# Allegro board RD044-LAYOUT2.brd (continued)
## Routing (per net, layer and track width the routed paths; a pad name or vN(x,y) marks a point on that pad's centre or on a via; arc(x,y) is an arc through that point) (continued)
/DI0_BI: length 29.5
  TOP w0.15: R74.2 18.75,3.7 18.75,9.75 19.73,10.72 19.73,11.07 ; 19.5,2.85 v1(19.5,1.9) ; 34.75,1.5 v3(34.75,2.1)
  TOP w0.25: CN3.51 34.75,1.5
  TOP w0.35: 19.73,11.07 IC11.2
  TOP w0.8: R74.2 19.5,2.85
  BOTTOM w0.15: v1(19.5,1.9) 21.5,3.9 32.15,3.9 32.35,4.1 34.4,4.1 34.75,3.75 v3(34.75,2.1)
/DI1_BI: length 22.5
  TOP w0.15: 34.75,5.85 34.75,6.75 32.7,8.8 v1(30.5,8.8) ; 19.5,8.65 v1(19.5,9.6) 20.38,10.47 20.38,11.07
  TOP w0.25: CN3.52 34.75,5.85
  TOP w0.35: 20.38,11.07 IC11.3
  TOP w0.8: R75.2 19.5,8.65
  BOTTOM w0.15: v1(30.5,8.8) 28.2,8.8 26,11 20.9,11 v1(19.5,9.6)
/DI2_BI: length 26.6
  TOP w0.15: 34.25,1.5 v3(34.25,3) ; 21.5,2.85 v1(21.5,1.9) ; 21.02,11.07 21.02,10.53 20.5,10 20.5,3.95 R76.2
  TOP w0.25: CN3.53 34.25,1.5
  TOP w0.35: 21.02,11.07 IC11.4
  TOP w0.8: R76.2 21.5,2.85
  BOTTOM w0.15: v3(34.25,3) 34.25,3.55 34,3.8 32.55,3.8 32.35,3.6 23.2,3.6 v1(21.5,1.9)
/DI3_BI: length 19.5
  TOP w0.15: 21.5,8.65 v1(21.5,9.6) 21.68,9.88 21.68,11.07 ; v1(31.5,8.2) 32.8,8.2 34.25,6.75 34.25,5.85
  TOP w0.25: CN3.54 34.25,5.85
  TOP w0.35: 21.68,11.07 IC11.5
  TOP w0.8: R77.2 21.5,8.65
  BOTTOM w0.15: v1(21.5,9.6) 22.6,10.7 25.8,10.7 28.3,8.2 v1(31.5,8.2)
/DI4_BI: length 23.5
  TOP w0.15: 22.32,11.07 22.32,9.93 22.5,9.75 22.5,3.95 R78.2 ; 33.75,1.5 v3(33.75,2.1) ; 23.5,2.85 v1(23.5,1.9)
  TOP w0.25: CN3.55 33.75,1.5
  TOP w0.35: 22.32,11.07 IC11.6
  TOP w0.8: R78.2 23.5,2.85
  BOTTOM w0.15: v1(23.5,1.9) 24.9,3.3 32.55,3.3 32.75,3.5 33.5,3.5 33.75,3.25 v3(33.75,2.1)
/DI5_BI: length 16.8
  TOP w0.15: 23.5,8.65 v1(23.5,9.6) 22.98,10.12 22.98,11.07 ; v1(30.5,7.6) 32.85,7.6 33.75,6.7 33.75,5.85
  TOP w0.25: CN3.56 33.75,5.85
  TOP w0.35: 22.98,11.07 IC11.7
  TOP w0.8: R79.2 23.5,8.65
  BOTTOM w0.15: v1(23.5,9.6) 24.25,10.35 25.65,10.35 28.4,7.6 v1(30.5,7.6)
/DI6_BI: length 20.8
  TOP w0.15: 33.25,1.5 v3(33.25,3) ; R80.2 24.5,3.95 24.5,10 23.62,10.88 23.62,11.07 ; 25.5,2.85 v1(25.5,1.9)
  TOP w0.25: CN3.57 33.25,1.5
  TOP w0.35: 23.62,11.07 IC11.8
  TOP w0.8: R80.2 25.5,2.85
  BOTTOM w0.15: v3(33.25,3) 26.6,3 v1(25.5,1.9)
/DI7_BI: length 14
  TOP w0.15: 33.25,5.85 33.25,6.75 33,7 v1(31.5,7) ; 25.5,8.65 v1(25.5,9.6) 24.27,10.82 24.27,11.07
  TOP w0.25: CN3.58 33.25,5.85
  TOP w0.35: 24.27,11.07 IC11.9
  TOP w0.8: R82.2 25.5,8.65
  BOTTOM w0.15: v1(25.5,9.6) 28.1,7 v1(31.5,7)
/DO0_BO: length 28.2
  TOP w0.15: 38.07,20.01 37.21,20.01 34.7,17.5 v1(33.5,17.5) 31,17.5 PAD8.1 ; 37.25,1.5 v3(37.25,3)
  TOP w0.25: CN3.41 37.25,1.5
  TOP w0.5: IC7.11 38.07,20.01
  BOTTOM w0.15: v3(37.25,3) 37.25,3.75 36.65,4.35 36.65,10.6 35.9,11.35 35.9,12.6 35.3,13.2 35.3,15.7 v1(33.5,17.5)
/DO1_BO: length 20.6
  TOP w0.15: 37.25,5.85 37.25,7 36.35,7.9 36.35,10.15 v3(36,10.5) ; 38.08,19.27 37.08,19.27 34.3,16.5 v1(33.5,16.5) PAD7.1
  TOP w0.25: CN3.42 37.25,5.85
  TOP w0.35: IC7.12 38.08,19.27
  BOTTOM w0.15: v3(36,10.5) 35.6,10.9 35.6,12.4 35,13 35,15 v1(33.5,16.5)
/DO2_BO: length 26.4
  TOP w0.15: 36.75,1.5 v3(36.75,2.1) ; PAD6.1 31,15.5 v1(33.5,15.5) 33.9,15.5 37.02,18.62 38.08,18.62
  TOP w0.25: CN3.43 36.75,1.5
  TOP w0.35: IC7.13 38.08,18.62
  BOTTOM w0.15: v3(36.75,2.1) 36.75,3.75 36.35,4.15 36.35,9.65 36,10 35.75,10 35.3,10.45 35.3,12.2 34.7,12.8 34.7,14.3 v1(33.5,15.5)
/DO3_BO: length 18.7
  TOP w0.15: 36.75,5.85 36.75,7 36.05,7.7 36.05,9.2 v3(35.75,9.5) ; PAD5.1 v1(33.5,14.5) 36.98,17.98 38.08,17.98
  TOP w0.25: CN3.44 36.75,5.85
  TOP w0.35: IC7.14 38.08,17.98
  BOTTOM w0.15: v3(35.75,9.5) 35,10.25 35,12 34.4,12.6 34.4,13.6 v1(33.5,14.5)
/DO4_BO: length 24.7
  TOP w0.15: 36.25,1.5 v3(36.25,3) ; 38.08,17.32 36.92,17.32 34.2,14.6 34.2,14.2 v1(33.5,13.5) 31,13.5 PAD4.1
  TOP w0.25: CN3.45 36.25,1.5
  TOP w0.35: IC7.15 38.08,17.32
  BOTTOM w0.15: v1(33.5,13.5) 34.1,12.9 34.1,12.4 34.7,11.8 34.7,9.8 35.5,9 35.75,9 36.05,8.7 36.05,3.95 36.25,3.75 v3(36.25,3)
/DO5_BO: length 17.2
  TOP w0.15: 38.08,16.68 36.88,16.68 34.6,14.4 34.6,13.6 v1(33.5,12.5) PAD3.1 ; v3(35.5,8.5) 35.75,8.25 35.75,7.5 36.25,7 36.25,5.85
  TOP w0.25: CN3.46 36.25,5.85
  TOP w0.35: IC7.16 38.08,16.68
  BOTTOM w0.15: v1(33.5,12.5) 34.4,11.6 34.4,9.6 v3(35.5,8.5)
/DO6_BO: length 23.2
  TOP w0.15: 35.75,1.5 v3(35.75,2.1) ; PAD2.1 31,11.5 v1(33.5,11.5) 35,13 35,14.2 36.83,16.02 38.08,16.02
  TOP w0.25: CN3.47 35.75,1.5
  TOP w0.35: IC7.17 38.08,16.02
  BOTTOM w0.15: v1(33.5,11.5) 34.1,10.9 34.1,9.15 35.25,8 35.5,8 35.75,7.75 v3(35.75,2.1)
/DO7_BO: length 15.8
  TOP w0.15: PAD1.1 v1(33.5,10.5) 35.4,12.4 35.4,14 36.77,15.38 38.08,15.38 ; 35.75,5.85 35.75,7 v3(35.25,7.5)
  TOP w0.25: CN3.48 35.75,5.85
  TOP w0.35: IC7.18 38.08,15.38
  BOTTOM w0.15: v3(35.25,7.5) 33.5,9.25 v1(33.5,10.5)
/PWM1A_BO: length 61.1
  TOP w0.15: 38.08,38.62 37.38,38.62 v1(36.5,39.5) 36.5,41.5 35.75,42.25 35.75,45.25 35,46 29.25,46 29,45.75 TP6.1 ; 41.25,1.5 v3(41.25,3)
  TOP w0.25: CN3.25 41.25,1.5
  TOP w0.35: IC5.13 38.08,38.62
  BOTTOM w0.15: v3(41.25,3) 41.25,6.75 41.75,7.25 41.75,9.75 44.65,12.65 44.65,30.85 42.45,33.05 41.05,33.05 40.75,33.35 40.75,35.25 v1(36.5,39.5)
/PWM1B_BO: length 47.9
  TOP w0.15: 38.08,37.98 37.02,37.98 v1(36.5,38.5) 35.9,39.1 35.9,41.1 34,43 TP5.1 ; 41.25,5.85 v3(41.25,9.2)
  TOP w0.25: CN3.26 41.25,5.85
  TOP w0.35: IC5.14 38.08,37.98
  BOTTOM w0.15: v3(41.25,9.2) 41.25,9.85 44.2,12.8 44.2,30.8 42.4,32.6 40.9,32.6 40.3,33.2 40.3,34.7 v1(36.5,38.5)
/PWM2A_BO: length 55.9
  TOP w0.15: TP4.1 29,40.75 29.25,41 35.25,41 35.5,40.75 35.5,38.5 v1(36.5,37.5) 36.78,37.33 38.08,37.33 ; 40.75,1.5 v3(40.75,2.1)
  TOP w0.25: CN3.27 40.75,1.5
  TOP w0.35: IC5.15 38.08,37.33
  BOTTOM w0.15: v1(36.5,37.5) 39.85,34.15 39.85,33.05 40.75,32.15 42.35,32.15 43.75,30.75 43.75,12.95 40.75,9.95 40.75,9 41.25,8.5 41.25,7.25 40.75,6.75 v3(40.75,2.1)
/PWM2B_BO: length 43
  TOP w0.15: 38.08,36.67 36.78,36.67 v1(36.5,36.5) 35.75,36.5 34,38.25 TP3.1 ; 40.75,5.85 v3(40.75,8.3)
  TOP w0.25: CN3.28 40.75,5.85
  TOP w0.35: IC5.16 38.08,36.67
  BOTTOM w0.15: v1(36.5,36.5) 39.4,33.6 39.4,32.9 40.6,31.7 42.3,31.7 43.3,30.7 43.3,13.1 40.45,10.25 40.45,8.6 v3(40.75,8.3)
/PWM3A_BO: length 52.1
  TOP w0.15: 40.25,1.5 v3(40.25,3) ; 38.08,36.02 37.02,36.02 v1(36.5,35.5) 36,36 29.25,36 29,35.75 TP2.1
  TOP w0.25: CN3.29 40.25,1.5
  TOP w0.35: IC5.17 38.08,36.02
  BOTTOM w0.15: v1(36.5,35.5) 37.8,34.2 37.8,32.3 38.85,31.25 42.25,31.25 42.85,30.65 42.85,13.25 40.15,10.55 40.15,8.2 40.75,7.6 40.75,7.2 40.25,6.7 v3(40.25,3)
/PWM3B_BO: length 40
  TOP w0.15: 40.25,5.85 v3(40.25,7.4) ; 38.08,35.38 37.38,35.38 v1(36.5,34.5) 34.15,34.5
  TOP w0.25: CN3.30 40.25,5.85
  TOP w0.35: IC5.18 38.08,35.38
  TOP w1.7: TP1.1 34.15,34.5
  BOTTOM w0.15: v1(36.5,34.5) 37.35,33.65 37.35,32.15 38.7,30.8 42.2,30.8 42.4,30.6 42.4,13.4 39.85,10.85 39.85,7.8 v3(40.25,7.4)
/PWM4A_BO: length 42.9
  TOP w0.15: TP12.1 29,30.75 29.25,31 35,31 v1(36.5,29.5) 37.38,28.62 38.08,28.62 ; 39.25,1.5 v3(39.25,3)
  TOP w0.25: CN3.33 39.25,1.5
  TOP w0.35: IC6.13 38.08,28.62
  BOTTOM w0.15: v1(36.5,29.5) 40.8,25.2 40.8,12.4 39.4,11 39.4,7 39.25,6.85 v3(39.25,3)
/PWM4B_BO: length 30.8
  TOP w0.15: 39.25,5.85 39.25,9.15 v3(38.9,9.5) ; 38.08,27.98 37.02,27.98 v1(36.5,28.5) 35.5,29.5 TP11.1
  TOP w0.25: CN3.34 39.25,5.85
  TOP w0.35: IC6.14 38.08,27.98
  BOTTOM w0.15: v1(36.5,28.5) 40.35,24.65 40.35,12.55 38.9,11.1 v3(38.9,9.5)
/PWM5A_BO: length 40.6
  TOP w0.15: TP10.1 29,25.75 30.75,27.5 v1(36.5,27.5) 36.78,27.32 38.08,27.32 ; 38.75,1.5 v3(38.75,2.1)
  TOP w0.25: CN3.35 38.75,1.5
  TOP w0.35: IC6.15 38.08,27.32
  BOTTOM w0.15: v3(38.75,2.1) 38.75,6.85 39,7.1 39,8.5 38.4,9.1 38.4,11.2 39.9,12.7 39.9,24.1 v1(36.5,27.5)
/PWM5B_BO: length 29.6
  TOP w0.15: TP9.1 34,25.75 34.75,26.5 v1(36.5,26.5) 36.78,26.68 38.08,26.68 ; v3(38.3,8.5) 38.75,8.05 38.75,5.85
  TOP w0.25: CN3.36 38.75,5.85
  TOP w0.35: IC6.16 38.08,26.68
  BOTTOM w0.15: v1(36.5,26.5) 39.45,23.55 39.45,12.85 38.05,11.45 38.05,8.75 v3(38.3,8.5)
/PWM6A_BO: length 39.5
  TOP w0.15: 38.25,1.5 v3(38.25,3) ; 38.08,26.02 37.02,26.02 v1(36.5,25.5) 35.5,24.5 35.5,23 34.25,21.75 30,21.75 29,20.75 TP8.1
  TOP w0.25: CN3.37 38.25,1.5
  TOP w0.35: IC6.17 38.08,26.02
  BOTTOM w0.15: v3(38.25,3) 38.25,6.85 38.5,7.1 38.5,7.6 37.7,8.4 37.7,11.7 37.8,11.8 37.8,24.2 v1(36.5,25.5)
/PWM6B_BO: length 28.5
  TOP w0.15: 38.25,5.85 38.25,7.15 v3(38,7.4) ; 38.08,25.38 37.38,25.38 v1(36.5,24.5) 35.9,23.9 35.9,22.65 34,20.75 TP7.1
  TOP w0.25: CN3.38 38.25,5.85
  TOP w0.35: IC6.18 38.08,25.38
  BOTTOM w0.15: v1(36.5,24.5) 37.35,23.65 37.35,8.05 v3(38,7.4)
/RESET_BO: length 52.3
  TOP w0.15: 38.46,42.3 37.7,42.3 37,43 PAD9.1 ; 38.55,42.05 v1(38.55,41) ; 35.25,1.5 v3(35.25,3)
  TOP w0.25: CN3.49 35.25,1.5
  TOP w0.5: 38.55,42.05 IC8.4 38.46,42.3
  BOTTOM w0.15: v1(38.55,41) 35,41 31.5,37.5 31.5,9.5 35.25,5.75 v3(35.25,3)
/RESET_SIG: length 34.5
  TOP w0.15: 59.25,53.13 v1(59.25,52)
  TOP w0.25: IC3.124 59.25,53.13 ; 39.5,44.95 v1(39.5,46)
  TOP w0.5: IC8.2 39.5,44.95
  BOTTOM w0.25: 37.3,52.1 37.3,48.2 v1(39.5,46) 41.5,48 52.25,48 57,52.75 58.5,52.75 v1(59.25,52) ; 37.3,52.36 37.3,53.35 37.45,53.5 IC2.4
  BOTTOM w0.8: 37.3,52.1 R7.2 37.3,52.36
AD0: length 47.4
  TOP w0.15: 45.25,1.5 v3(45.25,3)
  TOP w0.25: CN3.9 45.25,1.5
  BOTTOM w0.2: R50.2 78,4.2 54.6,4.2 50.1,8.7 46.3,8.7 45.45,7.85 45.45,4.45 45.25,4.25 v3(45.25,3)
AD1: length 55.5
  TOP w0.2: v1(83.5,7) 80.7,4.2 54.8,4.2 50.3,8.7 46.3,8.7 45.25,7.65 45.25,5.88
  TOP w0.25: CN3.10 45.25,5.88
  BOTTOM w0.2: v1(83.5,7) 83.5,16.2 R54.2
AD2: length 48.4
  TOP w0.15: 44.25,1.5 v3(44.25,3)
  TOP w0.25: CN3.13 44.25,1.5
  BOTTOM w0.2: v3(44.25,3) 44.25,4.75 44.55,5.05 44.55,8.25 46,9.7 50.7,9.7 55.2,5.2 69.45,5.2 70.5,6.25 70.5,16.2 R55.1
AD3: length 35
  TOP w0.2: 44.25,5.88 44.25,7.95 46,9.7 50.9,9.7 55.4,5.2 70.2,5.2 v1(72,7)
  TOP w0.25: CN3.14 44.25,5.88
  BOTTOM w0.2: 72,8.07 v1(72,7)
  BOTTOM w0.8: R51.1 72,8.07
AD4: length 35.3
  TOP w0.15: 43.25,1.5 v3(43.25,3)
  TOP w0.25: CN3.17 43.25,1.5
  BOTTOM w0.2: v3(43.25,3) 43.25,5.25 43.65,5.65 43.65,8.65 45.7,10.7 51.3,10.7 55.8,6.2 65.5,6.2 R62.2
AD5: length 43.2
  TOP w0.2: v1(68.75,7) 67.95,6.2 56,6.2 51.5,10.7 45.7,10.7 43.25,8.25 43.25,5.88
  TOP w0.25: 43.25,5.88 CN3.18
  BOTTOM w0.2: v1(68.75,7) 69,7.25 69,16.2 R66.2
AD6: length 28.5
  TOP w0.15: 42.25,1.5 v3(42.25,3)
  TOP w0.25: CN3.21 42.25,1.5
  BOTTOM w0.2: v3(42.25,3) 42.25,5.75 42.75,6.25 42.75,9.05 45.4,11.7 54.7,11.7 56.25,13.25 56.25,16.45 R67.1
AD7: length 21.3
  TOP w0.2: v1(56,8.2) 52.5,11.7 45.4,11.7 42.25,8.55 42.25,5.88
  TOP w0.25: 42.25,5.88 CN3.22
  BOTTOM w0.2: 57.37,8.2 v1(56,8.2)
  BOTTOM w0.8: R63.1 57.37,8.2
ADC01_P_DSP41: length 5.4
  TOP w0.2: 77.37,26.3 75.95,26.3 75.25,27 75.25,27.83 ; 78.87,26.3 77.63,26.3
  TOP w0.25: 75.25,27.83 IC3.41
  TOP w0.8: 77.37,26.3 C63.1 77.63,26.3 ; R58.1 78.87,26.3
ADC02_P_DSP39: length 5.4
  TOP w0.2: 74.63,24.55 75.87,24.55 ; 74.5,24.59 74.5,25.5 74.25,25.75 74.25,27.83
  TOP w0.25: 74.25,27.83 IC3.39
  TOP w0.8: 75.87,24.55 R60.1 ; 74.63,24.55 C65.1 74.5,24.59
ADC03_P_DSP48: length 3.9
  TOP w0.2: C64.1 79.95,31.75 79.17,31.75 ; 80.7,30.97 80.7,29.63
  TOP w0.25: IC3.48 79.17,31.75
  TOP w0.8: 80.7,29.63 R59.1 ; C64.1 80.7,30.97
ADC04_P_DSP44: length 6.6
  TOP w0.2: C66.1 79.6,27.2 77.05,27.2 76.81,27.43 76.81,27.79 ; 81.87,26.3 80.63,26.3
  TOP w0.35: 76.81,27.79 IC3.44
  TOP w0.8: 80.63,26.3 C66.1 ; R61.1 81.87,26.3
ADC05_P_DSP31: length 13.2
  TOP w0.2: 70.25,27.83 v1(70.25,25.75) 70,25.5 70,24.59 ; v1(75.25,25.75) 74.75,26.25 74.75,27.83 ; 68.63,24.55 69.87,24.55
  TOP w0.25: IC3.31 70.25,27.83 ; IC3.40 74.75,27.83
  TOP w0.8: 70,24.59 C72.1 69.87,24.55 ; R70.1 68.63,24.55
  BOTTOM w0.2: v1(70.25,25.75) v1(75.25,25.75)
ADC06_P_DSP29: length 32.2
  TOP w0.2: 65.63,24.55 66.87,24.55 ; v1(84.25,26.5) 84.25,31.25 83.25,32.25 79.17,32.25 ; C74.1 68.2,25.75 68.5,25.75 v1(69.25,26.5) 69.25,27.83
  TOP w0.25: IC3.29 69.25,27.83 ; 79.17,32.25 IC3.49
  TOP w0.8: R72.1 65.63,24.55 ; 66.87,24.55 C74.1
  BOTTOM w0.2: v1(84.25,26.5) v1(69.25,26.5)
ADC07_P_DSP56: length 7.8
  TOP w0.2: C73.1 83.55,36 80,36 79.75,35.75 79.17,35.75 ; 84.63,35.05 85.87,35.05
  TOP w0.25: 79.17,35.75 IC3.56
  TOP w0.8: 85.87,35.05 R71.1 ; C73.1 84.63,35.05
ADC08_P_DSP58: length 7.3
  TOP w0.2: 85.88,36.75 84.62,36.75 ; 84.38,36.75 79.17,36.75
  TOP w0.25: IC3.58 79.17,36.75
  TOP w0.7: 84.62,36.75 84.38,36.75 ; 86,36.75 85.88,36.75
BOOT1_DSP: length 30.1
  TOP w0.15: 34.66,61.13 33.87,61.13 33.75,61.25 33.15,61.25 ; 33.15,62.75 v1(34.5,62.75) ; 33.05,62.65 33.05,61.35
  TOP w0.7: SW2.3 34.66,61.13
  TOP w0.8: 33.05,61.35 R29.2 33.15,61.25 ; 33.15,62.75 R17.2 33.05,62.65
  BOTTOM w0.15: CN2.14 51.12,72.5 39.4,72.5 38.55,71.65 38.55,66.8 v1(34.5,62.75)
BOOT1_DSP139: length 34.3
  TOP w0.15: 52.83,48.75 52.25,48.75 52,48.5 47.9,48.5 44.8,51.6 v1(32,51.6) ; 31.35,61.25 v1(30.25,61.25)
  TOP w0.25: IC3.139 52.83,48.75
  TOP w0.8: R29.1 31.35,61.25
  BOTTOM w0.15: v1(32,51.6) 32,59.5 v1(30.25,61.25)
CANRX_A_DSP83: length 74.4
  TOP w0.15: 79.17,49.25 79.55,49.25 79.9,49.6 82.85,49.6 83.4,50.15 83.4,52.1 82.7,52.8 78.45,52.8 77.8,53.45 77.8,58.2 76.5,59.5 67.6,59.5 67.2,59.9 66.35,59.9 60.75,65.5 30,65.5 28.4,63.9 28.4,62.1 28.2,61.91 27.57,61.91
  TOP w0.25: 79.17,49.25 IC3.83
  TOP w0.6: IC12.4 27.57,61.91
CANTX_A_DSP84: length 80.4
  TOP w0.15: 28.3,56.6 28.3,57.9 28.11,58.09 27.57,58.09 ; 28.4,56.5 29.25,56.5 29.7,56.95 29.7,64.7 30.2,65.2 60.6,65.2 66.2,59.6 67.05,59.6 67.45,59.2 76.35,59.2 77.5,58.05 77.5,53.25 78.25,52.5 82.55,52.5 83.1,51.95 83.1,50.3 82.7,49.9 79.65,49.9 79.5,49.75 79.17,49.75
  TOP w0.25: IC3.84 79.17,49.75
  TOP w0.6: IC12.1 27.57,58.09
  TOP w0.8: 28.4,56.5 R83.2 28.3,56.6
CLK_20MHZ: length 2.9
  TOP w0.25: 59.75,56.35 IC3.123
  TOP w0.8: 59.75,56.5 59.75,56.35
DI0_DSP132: length 70
  TOP w0.15: 20.38,17.93 20.38,19.27 20.15,19.5 19.5,19.5 19,20 19,21.25 PAD10.1 21.95,24.2 24.45,24.2 25,24.75 25,49.5 28.6,53.1 35.4,53.1 36,52.5 55.05,52.5 55.19,52.63 55.19,53.11
  TOP w0.35: 55.19,53.11 IC3.132 ; IC11.18 20.38,17.93
DI1_DSP133: length 65.9
  TOP w0.15: 21.02,17.93 21.02,19.23 PAD11.1 20.85,21.1 20.85,22.6 22.15,23.9 24.6,23.9 25.3,24.6 25.3,49.3 28.8,52.8 35.2,52.8 35.8,52.2 51.93,52.2 52.31,51.81 52.81,51.81
  TOP w0.35: IC11.17 21.02,17.93 ; 52.81,51.81 IC3.133
DI2_DSP140: length 64.6
  TOP w0.15: 21.68,17.93 21.68,19.07 21.15,19.6 21.15,21.4 PAD12.1 23.35,23.6 24.75,23.6 25.6,24.45 25.6,49.1 27.5,51 44.5,51 47.65,47.85 52.05,47.85 52.45,48.25 52.83,48.25
  TOP w0.25: 52.83,48.25 IC3.140
  TOP w0.35: IC11.16 21.68,17.93
DI3_DSP141: length 63.6
  TOP w0.15: 22.32,17.93 22.32,18.98 22,19.3 PAD13.1 22.85,21.1 22.85,22.6 23.55,23.3 24.9,23.3 25.9,24.3 25.9,48.9 27.7,50.7 44.3,50.7 47.45,47.55 52.25,47.55 52.45,47.75 52.83,47.75
  TOP w0.25: 52.83,47.75 IC3.141
  TOP w0.35: IC11.15 22.32,17.93
DI4_DSP142: length 62
  TOP w0.15: 22.98,17.93 22.98,19.12 23.15,19.3 23.15,21.4 PAD14.1 24.75,23 25.05,23 26.2,24.15 26.2,48.7 27.9,50.4 44.1,50.4 47.25,47.25 52.83,47.25
  TOP w0.25: 52.83,47.25 IC3.142
  TOP w0.35: IC11.14 22.98,17.93
DI5_DSP143: length 61.2
  TOP w0.15: 23.62,17.93 23.62,18.88 24,19.25 PAD15.1 24.85,21.1 24.85,22.35 26.5,24 26.5,48.5 28.1,50.1 43.9,50.1 47.05,46.95 52.25,46.95 52.45,46.75 52.83,46.75
  TOP w0.25: 52.83,46.75 IC3.143
  TOP w0.35: IC11.13 23.62,17.93
DI6_DSP144: length 60.6
  TOP w0.15: 52.83,46.25 52.45,46.25 52.05,46.65 46.85,46.65 43.7,49.8 28.3,49.8 26.8,48.3 26.8,23.05 PAD16.1 25.15,21.4 25.15,19.9 24.27,19.02 24.27,17.93
  TOP w0.25: 52.83,46.25 IC3.144
  TOP w0.35: IC11.12 24.27,17.93
DI7_DSP145: length 59.9
  TOP w0.15: 25.01,17.93 25.01,19.26 PAD17.1 27.1,21.35 27.1,48.1 28.5,49.5 40.5,49.5 41.3,48.7 44.3,48.7 46.65,46.35 51.85,46.35 52.45,45.75 52.83,45.75
  TOP w0.25: 52.83,45.75 IC3.145
  TOP w0.5: IC11.11 25.01,17.93
DIO08_DSP94: length 69.3
  TOP w0.15: 13.9,38 15.69,38 ; 74.25,53.13 v1(74.25,52) ; 15.8,38.11 v1(15.8,39.2)
  TOP w0.25: IC3.94 74.25,53.13
  TOP w0.8: R96.2 13.9,38
  TOP w0.9: 15.69,38 D17.K/A 15.8,38.11
  BOTTOM w0.15: 16.7,39.2 v1(15.8,39.2) ; R88.2 17.9,40.3 27.8,40.3 32.6,45.1 51,45.1 52.1,46.2 57.95,46.2 61.85,50.1 69.35,50.1 72.15,52.9 73.35,52.9 v1(74.25,52)
  BOTTOM w0.8: R88.2 16.7,39.2
DIO09_DSP95: length 72
  TOP w0.15: 13.9,36 19.75,36 20.8,37.05 20.8,37.89 ; 20.8,38.11 v1(20.8,39.2) ; v1(73.65,51) 73.65,52.35 73.75,52.45 73.75,53.13
  TOP w0.25: IC3.95 73.75,53.13
  TOP w0.8: R98.2 13.9,36
  TOP w0.9: 20.8,37.89 D18.K/A 20.8,38.11
  BOTTOM w0.15: v1(73.65,51) 73.65,52.15 73.2,52.6 72.35,52.6 69.55,49.8 62.05,49.8 58.15,45.9 52.25,45.9 51.15,44.8 32.8,44.8 28,40 22.6,40 R89.2 ; 21.7,39.2 v1(20.8,39.2)
  BOTTOM w0.8: R89.2 21.7,39.2
DIO10_DSP96: length 69.1
  TOP w0.15: v1(73.05,52) 73.05,52.45 73.25,52.65 73.25,53.13 ; 13.9,34 15.69,34 ; 15.8,34.11 v1(15.8,35.2)
  TOP w0.25: IC3.96 73.25,53.13
  TOP w0.8: R99.2 13.9,34
  TOP w0.9: 15.8,34.11 D19.K/A 15.69,34
  BOTTOM w0.15: 16.7,35.2 v1(15.8,35.2) ; R90.2 17.9,36.3 24.8,36.3 33,44.5 51.3,44.5 52.4,45.6 58.35,45.6 62.25,49.5 69.75,49.5 72.25,52 v1(73.05,52)
  BOTTOM w0.8: R90.2 16.7,35.2
DIO11_DSP97: length 70.6
  TOP w0.15: 72.75,53.13 72.75,52.65 72.45,52.35 v1(72.45,51) ; 20.8,33.89 20.8,33.05 19.75,32 13.9,32 ; 20.8,34.11 v1(20.8,35.2)
  TOP w0.25: IC3.97 72.75,53.13
  TOP w0.8: R97.2 13.9,32
  TOP w0.9: 20.8,34.11 D20.K/A 20.8,33.89
  BOTTOM w0.15: R91.2 22.6,36 25,36 33.2,44.2 51.45,44.2 52.55,45.3 58.55,45.3 62.45,49.2 69.95,49.2 71.75,51 v1(72.45,51) ; 21.7,35.2 v1(20.8,35.2)
  BOTTOM w0.8: R91.2 21.7,35.2
DIO12_DSP171: length 56.3
  TOP w0.15: 15.8,30.11 v1(15.8,31.2) ; 52.83,32.75 52.5,32.75 v1(51.75,32) ; 13.9,30 15.69,30
  TOP w0.25: IC3.171 52.83,32.75
  TOP w0.8: R100.2 13.9,30
  TOP w0.9: 15.8,30.11 D21.K/A 15.69,30
  BOTTOM w0.15: R92.2 17.9,32.3 24.8,32.3 26.2,33.7 26.2,35.2 33.8,42.8 49.7,42.8 51.2,41.3 51.2,32.55 v1(51.75,32) ; 16.7,31.2 v1(15.8,31.2)
  BOTTOM w0.8: R92.2 16.7,31.2
DIO13_DSP172: length 58.7
  TOP w0.15: 20.8,29.89 20.8,29.05 19.75,28 13.9,28 ; 20.8,30.11 v1(20.8,31.2) ; v1(51.75,31) 52.3,31.55 52.3,32.05 52.5,32.25 52.83,32.25
  TOP w0.25: IC3.172 52.83,32.25
  TOP w0.8: R101.2 13.9,28
  TOP w0.9: 20.8,29.89 D22.K/A 20.8,30.11
  BOTTOM w0.15: v1(51.75,31) 50.9,31.85 50.9,41.1 49.5,42.5 34,42.5 26.5,35 26.5,33.5 25,32 22.6,32 R93.2 ; 21.7,31.2 v1(20.8,31.2)
  BOTTOM w0.8: R93.2 21.7,31.2
DIO14_DSP175: length 60.7
  TOP w0.15: v1(51.75,30) 52.5,30.75 52.83,30.75 ; 15.8,26.11 v1(15.8,27.2) ; 13.9,26 15.69,26
  TOP w0.25: IC3.175 52.83,30.75
  TOP w0.8: R102.2 13.9,26
  TOP w0.9: 15.8,26.11 D23.K/A 15.69,26
  BOTTOM w0.15: v1(51.75,30) 50.6,31.15 50.6,40.9 49.3,42.2 34.2,42.2 26.8,34.8 26.8,30.3 24.8,28.3 17.9,28.3 R94.2 ; 16.7,27.2 v1(15.8,27.2)
  BOTTOM w0.8: R94.2 16.7,27.2
DIO15_DSP176: length 62.9
  TOP w0.15: 20.8,26.11 v1(20.8,27.2) ; 52.89,30.18 52.5,30.18 52.3,29.98 52.3,29.55 v1(51.75,29) ; 13.9,24 19.6,24 20.8,25.2 20.8,25.89
  TOP w0.35: 53.35,30.18 52.89,30.18
  TOP w0.8: R103.2 13.9,24
  TOP w0.9: 20.8,25.89 D24.K/A 20.8,26.11
  BOTTOM w0.15: 21.7,27.2 v1(20.8,27.2) ; R95.2 22.6,28 25,28 27.1,30.1 27.1,34.6 34.4,41.9 49.1,41.9 50.3,40.7 50.3,30.45 v1(51.75,29)
  BOTTOM w0.8: R95.2 21.7,27.2
DO0_DSP8: length 20.5
  TOP w0.15: 58.75,27.83 58.75,27.5 58.95,27.3 58.95,26.45 58,25.5 54.5,25.5 52.5,23.5 52.5,21.75 51.75,21 47.45,21 R49.1 45.73,19.27 44.92,19.27
  TOP w0.25: 58.75,27.83 IC3.8
  TOP w0.35: IC7.9 44.92,19.27
DO1_DSP9: length 21.6
  TOP w0.15: 44.92,18.62 45.62,18.62 46.5,19.5 51.55,19.5 R48.1 ; 59.25,27.83 59.25,26.25 58.2,25.2 54.7,25.2 52.8,23.3 52.8,21.55 52.3,21.05 52.3,20.34
  TOP w0.25: 59.25,27.83 IC3.9
  TOP w0.35: IC7.8 44.92,18.62
  TOP w0.8: R48.1 52.3,20.34
DO2_DSP10: length 23.1
  TOP w0.15: R47.1 47.45,19 52.75,19 53.1,19.35 53.1,23.1 54.9,24.9 58.4,24.9 59.55,26.05 59.55,27.3 59.75,27.5 59.75,27.83 ; 46.6,18.25 46,18.25 45.73,17.98 44.92,17.98
  TOP w0.25: 59.75,27.83 IC3.10
  TOP w0.35: IC7.7 44.92,17.98
  TOP w0.8: 46.6,18.25 R47.1
DO3_DSP12: length 24.4
  TOP w0.15: 60.75,27.83 60.75,27.45 60.8,27.4 60.8,26.8 58.6,24.6 55.1,24.6 53.4,22.9 53.4,18.65 53,18.25 R46.1 51.55,17.5 46,17.5 45.83,17.32 44.92,17.32
  TOP w0.25: 60.75,27.83 IC3.12
  TOP w0.35: IC7.6 44.92,17.32
DO4_DSP13: length 25.9
  TOP w0.15: 44.92,16.68 46.27,16.68 R45.1 47.45,17 53,17 53.7,17.7 53.7,22.7 55.3,24.3 58.8,24.3 61.1,26.6 61.1,27.35 61.25,27.5 61.25,27.83
  TOP w0.25: 61.25,27.83 IC3.13
  TOP w0.35: IC7.5 44.92,16.68
DO5_DSP14: length 27
  TOP w0.15: 44.92,16.02 45.73,16.02 46.25,15.5 51.55,15.5 R44.1 ; 61.75,27.83 61.75,27.5 61.4,27.15 61.4,26.4 59,24 55.5,24 54,22.5 54,17 53.25,16.25 52.34,16.25
  TOP w0.25: 61.75,27.83 IC3.14
  TOP w0.35: 44.92,16.02 IC7.4
  TOP w0.8: R44.1 52.34,16.25
DO6_DSP22: length 31.8
  TOP w0.15: 44.92,15.38 45.58,15.38 R43.1 47.45,15 53,15 54.3,16.3 54.3,22.3 55.7,23.7 59.2,23.7 60.3,24.8 62.7,24.8 64.35,26.45 64.95,26.45 65.5,27 65.5,27.25 65.75,27.5 65.75,27.83
  TOP w0.25: 65.75,27.83 IC3.22
  TOP w0.35: IC7.3 44.92,15.38
DO7_DSP23: length 33.2
  TOP w0.15: 52.34,14.25 53.25,14.25 54.6,15.6 54.6,22.1 55.9,23.4 59.4,23.4 60.5,24.5 62.85,24.5 64.5,26.15 65.1,26.15 65.8,26.85 65.8,27.05 66.25,27.5 66.25,27.83 ; R42.1 51.55,13.5 46.25,13.5 45.9,13.85 45.9,14.35 45.52,14.72 44.92,14.72
  TOP w0.25: 66.25,27.83 IC3.23
  TOP w0.35: IC7.2 44.92,14.72
  TOP w0.8: R42.1 52.34,14.25
HSDT_/RESET: length 21.1
  TOP w0.15: 44,58.69 v1(44,57.5)
  TOP w1: SW1.2 44,58.69
  BOTTOM w0.15: 45.1,57.5 v1(44,57.5) 43.4,58.1 42.1,58.1 42,58 41.59,58 ; 45.2,57.6 45.2,64.7 48.5,68 48.5,69.96 CN2.12
  BOTTOM w0.25: IC1.1 41.59,58
  BOTTOM w0.8: 45.2,57.6 R1.2 45.1,57.5
PWM1A_DSP160: length 11.4
  TOP w0.15: 44.92,37.98 45.38,37.98 46,38.6 46,39.55 R35.1 47.45,39.5 49.75,39.5 51.1,38.15 52.15,38.15 52.25,38.25 52.83,38.25
  TOP w0.25: 52.83,38.25 IC3.160
  TOP w0.35: 44.92,37.98 IC5.7
PWM1B_DSP161: length 10
  TOP w0.15: 44.92,37.33 45.27,37.33 R34.1 47.45,38 50.25,38 50.4,37.85 52.15,37.85 52.25,37.75 52.83,37.75
  TOP w0.25: 52.83,37.75 IC3.161
  TOP w0.35: IC5.6 44.92,37.33
PWM2A_DSP162: length 9.8
  TOP w0.15: 52.83,37.25 52.5,37.25 51.75,36.5 47.45,36.5 R33.1 46.12,36.67 44.92,36.67
  TOP w0.25: 52.83,37.25 IC3.162
  TOP w0.35: IC5.5 44.92,36.67
PWM2B_DSP163: length 10.1
  TOP w0.15: 52.83,36.75 52.45,36.75 51.85,36.15 50.9,36.15 49.75,35 47.45,35 R32.1 ; 46.6,35.75 46,35.75 45.73,36.02 44.92,36.02
  TOP w0.25: 52.83,36.75 IC3.163
  TOP w0.35: IC5.4 44.92,36.02
  TOP w0.8: 46.6,35.75 R32.1
PWM3A_DSP164: length 11.5
  TOP w0.15: 44.92,35.38 45.58,35.38 R31.1 47.45,33.5 49.75,33.5 50.1,33.85 50.1,34.85 51.1,35.85 52,35.85 52.4,36.25 52.83,36.25
  TOP w0.25: 52.83,36.25 IC3.164
  TOP w0.35: 44.92,35.38 IC5.3
PWM3B_DSP165: length 13.1
  TOP w0.15: 52.83,35.75 52.35,35.75 52.15,35.55 51.3,35.55 50.4,34.65 50.4,32.65 49.75,32 47.45,32 R30.1 46,33.45 46,34 45.27,34.73 44.92,34.73
  TOP w0.25: 52.83,35.75 IC3.165
  TOP w0.35: IC5.2 44.92,34.73
PWM4A_DSP166: length 14
  TOP w0.15: 44.92,27.98 45.38,27.98 46,28.6 46,29.55 R41.1 47.45,31 49.75,31 50.7,31.95 50.7,34.45 51.5,35.25 52.83,35.25
  TOP w0.25: 52.83,35.25 IC3.166
  TOP w0.35: 44.92,27.98 IC6.7
PWM4B_DSP167: length 14.2
  TOP w0.15: 52.83,34.75 52.35,34.75 52.15,34.95 51.7,34.95 51,34.25 51,30.75 49.75,29.5 47.45,29.5 R40.1 45.27,27.32 44.92,27.32
  TOP w0.25: 52.83,34.75 IC3.167
  TOP w0.35: IC6.6 44.92,27.32
PWM5A_DSP18: length 23.3
  TOP w0.15: v1(47.45,28) R39.1 46.12,26.68 44.92,26.68 ; 63.75,27.83 63.75,27.45 63.85,27.35 63.85,26.85 63.4,26.4 62.15,26.4 v1(61.5,25.75)
  TOP w0.25: IC3.18 63.75,27.83
  TOP w0.35: IC6.5 44.92,26.68
  BOTTOM w0.15: v1(47.45,28) 48.95,26.5 50,26.5 51.2,25.3 61.05,25.3 v1(61.5,25.75)
PWM5B_DSP19: length 23.2
  TOP w0.15: 64.25,27.83 64.25,27.45 64.15,27.35 64.15,26.7 63.55,26.1 62.85,26.1 v1(62.5,25.75) ; 44.92,26.02 45.73,26.02 46,25.75 R38.1 v1(47.45,26.5)
  TOP w0.25: IC3.19 64.25,27.83
  TOP w0.35: 44.92,26.02 IC6.4
  BOTTOM w0.15: v1(47.45,26.5) 48.95,25 61.75,25 v1(62.5,25.75)
PWM6A_DSP1: length 13.5
  TOP w0.15: 55.19,27.81 55.19,27.48 55,27.3 53.05,27.3 50.75,25 47.45,25 R37.1 45.58,25.38 44.92,25.38
  TOP w0.35: 55.19,27.81 IC3.1 ; 44.92,25.38 IC6.3
PWM6B_DSP2: length 15.3
  TOP w0.15: 44.92,24.73 45.27,24.73 46,24 46,23.45 R36.1 47.45,23.5 49.75,23.5 53.25,27 55.3,27 55.75,27.45 55.75,27.83
  TOP w0.25: 55.75,27.83 IC3.2
  TOP w0.35: IC6.2 44.92,24.73
SCIRX_B_DSP157: length 38.5
  TOP w0.15: 52.83,39.75 51.75,39.75 50,41.5 47.5,41.5 41.8,47.2 28.75,47.2 v1(28,47.95)
  TOP w0.25: IC3.157 52.83,39.75
  BOTTOM w0.15: v1(28,47.95) 18.45,47.95
  BOTTOM w0.5: 18.45,47.95 IC14.4
SCIRXDA_DSP155: length 50.6
  TOP w0.15: 52.83,40.75 51.75,40.75 50.4,42.1 47.9,42.1 42.2,47.8 33.45,47.8 v1(33,48.25) ; 33.15,64.25 v1(34.5,64.25)
  TOP w0.25: IC3.155 52.83,40.75
  TOP w0.8: R15.1 33.15,64.25
  BOTTOM w0.15: CN2.2 38.25,70.13 38.25,68 v1(34.5,64.25) 33,62.75 v1(33,48.25)
SCITX_B_DSP156: length 41.5
  TOP w0.15: v1(29,47.95) 29.45,47.5 42,47.5 47.7,41.8 50.2,41.8 51.75,40.25 52.83,40.25
  TOP w0.25: IC3.156 52.83,40.25
  BOTTOM w0.15: 20.7,53.9 20.7,52.8 25,48.5 28.45,48.5 v1(29,47.95) ; 18.45,54 20.6,54
  BOTTOM w0.5: IC13.2 18.45,54
  BOTTOM w0.8: 20.6,54 R84.2 20.7,53.9
SCITXDA_DSP154: length 52.3
  TOP w0.15: 52.83,41.25 51.75,41.25 50.6,42.4 48.1,42.4 42.4,48.1 34.4,48.1 33.7,48.8 v1(31,48.8) ; 31.35,59.75 v1(30.25,59.75)
  TOP w0.25: IC3.154 52.83,41.25
  TOP w0.8: R28.1 31.35,59.75
  BOTTOM w0.15: CN2.1 33.48,68.73 29.7,64.95 29.7,60.3 v1(30.25,59.75) 31,59 v1(31,48.8)
SCL_A_DSP131: length 19.4
  TOP w0.15: 55.75,54.17 55.75,54.5 55.6,54.65 54.9,54.65 53.55,53.3 v1(50,53.3) ; 48.28,62.63 v1(47.25,62.63)
  TOP w0.25: 55.75,54.17 IC3.131
  TOP w0.6: IC4.6 48.28,62.63
  BOTTOM w0.15: v1(50,53.3) 50,58.75 48.7,60.05 48.7,60.97 ; R20.1 47.37,62.33 v1(47.25,62.63)
  BOTTOM w0.8: R20.1 48.7,60.97
SDA_A_DSP130: length 24.5
  TOP w0.15: 56.25,54.17 56.25,54.5 55.8,54.95 54.7,54.95 53.65,53.9 49.6,53.9 v1(49,53.3) ; 48.28,63.91 v1(47.25,63.91)
  TOP w0.25: 56.25,54.17 IC3.130
  TOP w0.6: IC4.5 48.28,63.91
  BOTTOM w0.15: R21.1 47.5,63.7 v1(47.25,63.91) 46.7,63.35 46.7,61.55 49,59.25 v1(49,53.3)
SPISTEA_DSP107: length 41.6
  TOP w0.15: 67.75,53.13 67.75,52.5 v1(67.25,52) ; CN2.8 46,70 46,68 46.7,67.3 63.3,67.3 v1(64,68)
  TOP w0.25: IC3.107 67.75,53.13
  BOTTOM w0.15: v1(64,68) 64,59.5 67.25,56.25 v1(67.25,52)
SSCK_DSP105: length 45.9
  TOP w0.15: 68.75,53.13 68.75,52.5 v1(68.25,52) ; CN2.6 43.5,69.96 43.5,68 44.5,67 64,67 v1(65,68)
  TOP w0.25: IC3.105 68.75,53.13
  BOTTOM w0.15: v1(65,68) 64.3,67.3 64.3,60.95 65.85,59.4 65.85,58.15 67.65,56.35 67.65,52.6 v1(68.25,52)
SSI_DSP104: length 42.2
  TOP w0.15: 63,69.1 v1(63,68) 62.6,67.6 48.9,67.6 48.5,68 48.5,70.04 CN2.10 ; 69.25,53.13 v1(69.25,52)
  TOP w0.25: IC3.104 69.25,53.13
  TOP w0.8: R16.1 63,69.1
  BOTTOM w0.15: v1(63,68) 63.7,67.3 63.7,59.3 66.7,56.3 66.7,51.7 67,51.4 68.65,51.4 v1(69.25,52)
SSO_DSP103: length 47.9
  TOP w0.15: v1(70.25,52) 69.75,52.5 69.75,53.13 ; v1(65,67) 64.7,66.7 42.3,66.7 41,68 41,69.92 CN2.4
  TOP w0.25: IC3.103 69.75,53.13
  BOTTOM w0.15: v1(65,67) 64.6,66.6 64.6,61.15 66.15,59.6 66.15,58.35 68.05,56.45 68.05,54.2 v1(70.25,52)
TCK_DSP81: length 31.2
  TOP w0.15: 79.17,48.25 79.7,48.25 80,47.95 v1(80,47) ; 80.2,64.89 v1(80.2,63.8) ; 80.2,65.11 80.2,66.2 81.08,67.08 CN1.11
  TOP w0.25: IC3.81 79.17,48.25
  TOP w0.9: 80.2,65.11 D5.K/A 80.2,64.89
  BOTTOM w0.15: R10.2 77,61.6 77,53.2 79.5,50.7 79.5,47.5 v1(80,47) ; 79.3,63.8 v1(80.2,63.8) ; CN1.9 CN1.11
  BOTTOM w0.8: R10.2 79.3,63.8
TDI_DSP77: length 31
  TOP w0.15: CN1.3 74,66.65 74,62.7 D3.K/A ; 78.13,46.25 77.5,46.25 77.35,46.4 76.6,46.4 v1(76,47) ; 75.2,61.39 v1(75.2,60.3)
  TOP w0.25: 78.13,46.25 IC3.77
  TOP w0.9: D3.K/A 75.2,61.39
  BOTTOM w0.15: 74.3,60.3 v1(75.2,60.3) 75.7,59.8 75.7,52.05 77.9,49.85 77.9,47.9 77.6,47.6 76.6,47.6 v1(76,47)
  BOTTOM w0.8: R9.2 74.3,60.3
TDO_DSP78: length 26.8
  TOP w0.15: v1(77,47) 77.5,47 77.75,46.75 78.13,46.75 ; 75.2,65.11 75.2,67 76,67.8 CN1.7 ; 75.2,64.89 v1(75.2,63.8)
  TOP w0.25: IC3.78 78.13,46.75
  TOP w0.9: 75.2,65.11 D4.K/A 75.2,64.89
  BOTTOM w0.15: v1(75.2,63.8) 76,63 76,52.25 78.2,50.05 78.2,47.7 77.5,47 v1(77,47)
TMS_DSP80: length 29.1
  TOP w0.15: v1(77,48.5) 77.75,47.75 78.13,47.75 ; CN1.1 68.38,67.62 69,67 69,62.7 D1.K/A ; 70.2,61.39 v1(70.2,60.3)
  TOP w0.25: IC3.80 78.13,47.75
  TOP w0.9: D1.K/A 70.2,61.39
  BOTTOM w0.15: 69.3,60.3 v1(70.2,60.3) 70.55,59.95 70.55,55.2 71.95,53.8 74.2,53.8 75.1,52.9 75.1,51.65 77,49.75 v1(77,48.5)
  BOTTOM w0.8: R8.2 69.3,60.3
TRST_DSP79: length 35.4
  TOP w0.15: v1(76,48.5) 76.9,47.6 77.4,47.6 77.75,47.25 78.13,47.25 ; 70.2,65.11 70.2,67.3 69.65,67.85 69.65,71 CN1.2 ; 70.2,64.89 v1(70.2,63.8)
  TOP w0.25: IC3.79 78.13,47.25
  TOP w0.9: 70.2,65.11 D2.K/A 70.2,64.89
  BOTTOM w0.15: v1(76,48.5) 76.6,47.9 77.4,47.9 77.6,48.1 77.6,49.65 75.4,51.85 75.4,53.1 74.4,54.1 72.15,54.1 70.85,55.4 70.85,63.15 v1(70.2,63.8) 69.3,63.8
  BOTTOM w0.8: R14.1 69.3,63.8
N16607086: length 4.4
  BOTTOM w0.25: IC1.4 40.45,57 40.3,56.85 40.3,55.86 ; 40.3,55.6 40.3,55 40,54.7 39.2,54.7 39,54.5 IC2.1
  BOTTOM w0.8: 40.3,55.86 R5.2 40.3,55.6
N16607090: length 4.5
  BOTTOM w0.25: 38.7,50.6 38.7,49.4 ; 38.7,52.1 38.7,50.9 ; IC2.3 38.55,53.5 38.7,53.35 38.7,52.36
  BOTTOM w0.8: 38.7,52.1 C4.1 38.7,52.36 ; 38.7,50.6 R4.1 38.7,50.9 ; 38.7,49.4 R2.2
N16607182: length 4.5
  BOTTOM w0.25: 41.7,55.86 41.7,56.85 41.55,57 IC1.3 ; 41.7,54.1 41.7,52.9 ; 41.7,55.6 41.7,54.4
  BOTTOM w0.8: 41.7,54.4 R3.1 41.7,54.1 ; 41.7,55.86 C2.1 41.7,55.6 ; 41.7,52.9 R6.2
N16607194: length 1.4
  BOTTOM w0.25: IC1.5 39.66,57.5 C3.1
N16607210: length 1.3
  BOTTOM w0.25: C5.1 36.73,54 IC2.5
N16608626: length 6.2
  BOTTOM w0.15: 74.15,63.9 74.15,66.85 73.46,67.54 CN1.5
  BOTTOM w0.8: R11.2 74.15,63.9
N16609034: length 4.2
  TOP w0.15: CN1.13 83.62,67.62 83,67 83,65.9
  TOP w0.8: R12.2 83,65.9
N16609038: length 7
  TOP w0.15: CN1.14 85,70.89 85,65.9
  TOP w0.8: R13.2 85,65.9
N16609736: length 6.6
  TOP w0.15: R19.2 64.65,55.6 62.85,55.6 61.75,54.5 61.75,54.17 ; 65.35,56.2 66.65,56.2
  TOP w0.25: IC3.119 61.75,54.17
  TOP w0.8: 66.65,56.2 R18.2 ; R19.2 65.35,56.2
N16610346: length 14.2
  TOP w0.3: 50.45,58.5 51.12,58.5
  TOP w0.45: C17.1 51.12,58.5
  TOP w0.5: 49.77,60.09 50.1,60.09 v1(50.45,59.75) 50.45,57.51 ; 48.91,55.75 50.19,55.75 ; 50.45,56.99 50.45,56.01
  TOP w0.6: 49.77,60.09 IC4.8
  TOP w0.8: 50.45,56.01 C19.1 50.19,55.75 ; 50.45,56.99 C18.1 50.45,57.51 ; D6.K 48.91,55.75
  BOTTOM w0.3: 50.34,62.5 51.25,62.5 51.5,62.25 51.5,61 ; 51.5,61 51.5,60 51.25,59.75 v1(50.45,59.75) ; 51.5,61 50.47,61
  BOTTOM w0.8: 50.34,62.5 R21.2 ; R20.2 50.47,61
N16610376: length 2.4
  TOP w0.15: 56.72,60.09 57.55,60.09 R22.2
  TOP w0.6: 56.72,60.09 IC4.1
N16610420: length 2.5
  TOP w0.15: 56.72,61.37 57.31,61.37 R23.2
  TOP w0.6: 56.72,61.37 IC4.2
N16610428: length 2.2
  TOP w0.15: 46.88,61.37 48.28,61.37
  TOP w0.6: 46.75,61.37 46.88,61.37 ; 48.28,61.37 IC4.7
N16610486: length 2.8
  TOP w0.15: R24.2 57.5,63.05 57.5,62.8 57.34,62.63 56.72,62.63
  TOP w0.6: 56.72,62.63 IC4.3
N16610930: length 3.4
  TOP w0.15: 34.66,59.87 33.87,59.87 33.75,59.75 33.15,59.75 ; 33.05,58.35 33.05,59.65
  TOP w0.7: SW2.4 34.66,59.87
  TOP w0.8: R26.2 33.05,58.35 ; 33.05,59.65 R28.2 33.15,59.75
N16624647: length 8
  TOP w0.2: v1(72.7,13.75) 73.01,13.85 73.58,13.85
  TOP w0.35: IC9.12 73.58,13.85
  BOTTOM w0.2: 73.7,12.12 73.7,9.87 ; 73.42,9.75 72.12,9.75 ; 73.64,13.75 v1(72.7,13.75) ; 73.7,12.38 73.7,13.62
  BOTTOM w0.7: 73.7,9.87 73.7,9.75 ; 72.12,9.75 72,9.75
  BOTTOM w0.8: 73.7,12.38 R53.1 73.7,12.12 ; 73.7,13.62 C59.1 73.64,13.75
  BOTTOM w0.9: D8.K/A 73.42,9.75
N16624651: length 8
  TOP w0.2: v1(81.3,13.75) 80.99,13.85 80.42,13.85
  TOP w0.35: IC9.3 80.42,13.85
  BOTTOM w0.2: 80.3,13.62 80.3,12.38 ; 80.58,9.75 81.88,9.75 ; 80.3,12.12 80.3,9.87 ; 80.36,13.75 v1(81.3,13.75)
  BOTTOM w0.7: 80.3,9.87 80.3,9.75 ; 81.88,9.75 82,9.75
  BOTTOM w0.8: 80.36,13.75 C58.1 80.3,13.62 ; 80.3,12.38 R52.1 80.3,12.12
  BOTTOM w0.9: D7.K/A 80.58,9.75
N16624783: length 25.6
  TOP w0.2: 79,24.57 79,23 83,19 83,10.75 82.5,10.25 80,10.25 78.7,11.55 78.7,12.25 78.91,12.46 79.35,12.46 ; 80.45,12.46 80.96,12.46 81.1,12.6 81.1,13.05 80.95,13.2 80.42,13.2
  TOP w0.35: IC9.2 80.42,13.2
  TOP w0.5: 80.45,12.46 IC9.1 79.35,12.46
  TOP w0.8: R58.2 79,24.57
N16624799: length 30.3
  TOP w0.2: 73.58,13.2 73.05,13.2 72.9,13.05 72.9,12.6 73.04,12.46 73.55,12.46 ; 74.65,12.46 75.1,12.46 75.3,12.26 75.3,10.45 76.25,9.5 82.75,9.5 83.8,10.55 83.8,20.2 82,22 82,24.57
  TOP w0.35: IC9.13 73.58,13.2
  TOP w0.5: 73.55,12.46 IC9.14 74.65,12.46
  TOP w0.8: R61.2 82,24.57
N16625013: length 8
  TOP w0.2: 80.42,15.15 80.99,15.15 v1(81.3,15.25)
  TOP w0.35: IC9.5 80.42,15.15
  BOTTOM w0.2: 80.3,16.62 80.3,15.38 ; 80.58,19.25 81.88,19.25 ; 80.3,16.88 80.3,19.13 ; 80.36,15.25 v1(81.3,15.25)
  BOTTOM w0.7: 81.88,19.25 82,19.25 ; 80.3,19.13 80.3,19.25
  BOTTOM w0.8: 80.3,16.88 R56.1 80.3,16.62 ; 80.3,15.38 C61.1 80.36,15.25
  BOTTOM w0.9: D9.K/A 80.58,19.25
N16625021: length 8
  TOP w0.2: v1(72.7,15.25) 73.01,15.15 73.58,15.15
  TOP w0.35: IC9.10 73.58,15.15
  BOTTOM w0.2: 73.7,15.38 73.7,16.62 ; 73.64,15.25 v1(72.7,15.25) ; 73.42,19.25 72.12,19.25 ; 73.7,16.88 73.7,19.13
  BOTTOM w0.7: 73.7,19.13 73.7,19.25 ; 72.12,19.25 72,19.25
  BOTTOM w0.8: 73.7,16.88 R57.1 73.7,16.62 ; 73.64,15.25 C62.1 73.7,15.38
  BOTTOM w0.9: D10.K/A 73.42,19.25
N16625097: length 12.5
  TOP w0.2: 80.45,16.54 80.96,16.54 81.1,16.4 81.1,15.95 80.95,15.8 80.42,15.8 ; R60.2 76.5,22.45 78.05,22.45 78.75,21.75 78.75,16.69 78.9,16.54 79.35,16.54
  TOP w0.35: IC9.6 80.42,15.8
  TOP w0.5: 79.35,16.54 IC9.7 80.45,16.54
N16625113: length 24
  TOP w0.2: v1(83.5,22.5) 83.5,28.3 R59.2 ; 73.55,16.54 73.04,16.54 72.9,16.4 72.9,15.95 73.05,15.8 73.58,15.8 ; v1(77,21.25) 75.25,19.5 75.25,16.7 75.09,16.54 74.65,16.54
  TOP w0.35: IC9.9 73.58,15.8
  TOP w0.5: 74.65,16.54 IC9.8 73.55,16.54
  BOTTOM w0.2: v1(83.5,22.5) 78.25,22.5 v1(77,21.25)
N16625873: length 8
  TOP w0.2: 65.92,13.85 66.49,13.85 v1(66.8,13.75)
  TOP w0.35: IC10.3 65.92,13.85
  BOTTOM w0.2: 65.8,13.62 65.8,12.38 ; 65.86,13.75 v1(66.8,13.75) ; 66.08,9.75 67.38,9.75 ; 65.8,12.12 65.8,9.87
  BOTTOM w0.7: 67.38,9.75 67.5,9.75 ; 65.8,9.87 65.8,9.75
  BOTTOM w0.8: 65.8,12.12 R64.1 65.8,12.38 ; 65.8,13.62 C67.1 65.86,13.75
  BOTTOM w0.9: D11.K/A 66.08,9.75
N16626013: length 22.2
  TOP w0.2: 68.5,22.82 68.5,10.75 68,10.25 65.5,10.25 64.2,11.55 64.2,12.25 64.41,12.46 64.85,12.46 ; 65.95,12.46 66.46,12.46 66.6,12.6 66.6,13.05 66.45,13.2 65.92,13.2
  TOP w0.35: IC10.2 65.92,13.2
  TOP w0.5: 65.95,12.46 IC10.1 64.85,12.46
  TOP w0.8: 68.5,22.82 R70.2
N16626029: length 58.2
  TOP w0.2: v1(86,24.25) 86,31.25 87,32.25 87,37.3 R73.2 ; 60.15,12.46 60.6,12.46 60.8,12.26 60.8,10.2 61.5,9.5 68.25,9.5 70,11.25 v1(70,20.5) ; 59.08,13.2 58.55,13.2 58.4,13.05 58.4,12.6 58.54,12.46 59.05,12.46
  TOP w0.35: IC10.13 59.08,13.2
  TOP w0.5: 60.15,12.46 IC10.14 59.05,12.46
  BOTTOM w0.2: v1(86,24.25) 75,24.25 73.5,22.75 72.25,22.75 v1(70,20.5)
N16626045: length 8
  TOP w0.2: v1(58.2,13.75) 58.51,13.85 59.08,13.85
  TOP w0.35: IC10.12 59.08,13.85
  BOTTOM w0.2: 58.92,9.75 57.62,9.75 ; 59.2,12.12 59.2,9.87 ; 59.2,12.38 59.2,13.62 ; 59.14,13.75 v1(58.2,13.75)
  BOTTOM w0.7: 59.2,9.87 59.2,9.75 ; 57.62,9.75 57.5,9.75
  BOTTOM w0.8: 59.2,12.12 R65.1 59.2,12.38 ; 59.14,13.75 C68.1 59.2,13.62
  BOTTOM w0.9: D12.K/A 58.92,9.75
N16626273: length 8
  TOP w0.2: v1(66.8,15.25) 66.49,15.15 65.92,15.15
  TOP w0.35: IC10.5 65.92,15.15
  BOTTOM w0.2: 65.86,15.25 v1(66.8,15.25) ; 65.8,16.62 65.8,15.38 ; 65.8,16.88 65.8,19.13 ; 66.08,19.25 67.38,19.25
  BOTTOM w0.7: 67.38,19.25 67.5,19.25 ; 65.8,19.13 65.8,19.25
  BOTTOM w0.8: 65.86,15.25 C70.1 65.8,15.38 ; 65.8,16.62 R68.1 65.8,16.88
  BOTTOM w0.9: D13.K/A 66.08,19.25
N16626281: length 8
  TOP w0.2: 59.08,15.15 58.51,15.15 v1(58.2,15.25)
  TOP w0.35: IC10.10 59.08,15.15
  BOTTOM w0.2: 58.92,19.25 57.62,19.25 ; 59.14,15.25 v1(58.2,15.25) ; 59.2,16.88 59.2,19.13 ; 59.2,15.38 59.2,16.62
  BOTTOM w0.7: 59.2,19.13 59.2,19.25 ; 57.62,19.25 57.5,19.25
  BOTTOM w0.8: 59.2,16.62 R69.1 59.2,16.88 ; 59.2,15.38 C71.1 59.14,15.25
  BOTTOM w0.9: D14.K/A 58.92,19.25
N16626357: length 11
  TOP w0.2: 64.85,16.54 64.4,16.54 64.25,16.69 64.25,21.7 R72.2 ; 65.95,16.54 66.46,16.54 66.6,16.4 66.6,15.95 66.45,15.8 65.92,15.8
  TOP w0.35: IC10.6 65.92,15.8
  TOP w0.5: 64.85,16.54 IC10.7 65.95,16.54
N16626365: length 42.4
  TOP w0.2: 86,33.32 86,32.5 85,31.5 v1(85,25) ; 60.15,16.54 60.59,16.54 60.75,16.7 60.75,19.5 v1(62.5,21.25) ; 59.08,15.8 58.55,15.8 58.4,15.95 58.4,16.4 58.54,16.54 59.05,16.54
  TOP w0.35: IC10.9 59.08,15.8
  TOP w0.5: 60.15,16.54 IC10.8 59.05,16.54
  TOP w0.8: 86,33.32 R71.2
  BOTTOM w0.2: v1(62.5,21.25) 66.25,25 v1(85,25)
N16642513: length 4.5
  TOP w0.5: PAD22.1 90.69,21.5 ; C95.1 91.55,22.1 IC15.1
  TOP w0.8: 90.69,21.5 C95.1
N16664780: length 5.1
  TOP w0.15: v1(14.7,53.05) 15.65,53.05 15.8,53.2 D15.K/A ; 13.9,54 15.69,54
  TOP w0.8: R85.2 13.9,54
  TOP w0.9: 15.69,54 D15.K/A
  BOTTOM w0.15: v1(14.7,53.05) 15.55,53.05
  BOTTOM w0.5: 15.55,53.05 IC13.4
N16668564: length 11.4
  TOP w0.15: 15.8,50.61 v1(15.8,51.75) ; R87.2 13.8,51.2 14.5,50.5 15.69,50.5
  TOP w0.9: 15.8,50.61 D16.K/A 15.69,50.5
  BOTTOM w0.15: 15.55,47 14.9,47 14.55,47.35 14.55,51.65 ; 14.65,51.75 v1(15.8,51.75)
  BOTTOM w0.5: IC14.2 15.55,47
  BOTTOM w0.8: 14.65,51.75 R86.2 14.55,51.65
N16668568: length 3
  TOP w0.15: 10.11,52 12.1,52
  TOP w0.8: 12.1,52 R87.1
  TOP w1: CN6.3 10.11,52
N16669496: length 9.5
  TOP w0.15: 22,64.89 22,64 22.3,63.7 23.3,63.7 24,63 24,60 23.36,59.37 22.7,59.37
  TOP w0.6: IC12.7 22.7,59.37
  TOP w1: 22,64.89 CN4.1
N16669500: length 9.5
  TOP w0.15: 22.7,60.63 23.34,60.63 23.6,60.9 23.6,62.8 23.1,63.3 20.7,63.3 20,64 20,64.89
  TOP w0.6: IC12.6 22.7,60.63
  TOP w1: 20,64.89 CN4.2
N16671270: length 3
  TOP w0.15: 10.11,54 12.1,54
  TOP w0.8: 12.1,54 R85.1
  TOP w1: CN6.2 10.11,54
N16690596: length 1.5
  TOP w0.5: 95.2,60.76 95.2,61.74
  TOP w0.8: 95.2,61.74 LED1.A ; R81.2 95.2,60.76
N16817849: length 3
  TOP w0.15: 12.1,24 10.11,24
  TOP w0.8: R103.1 12.1,24
  TOP w1: 10.11,24 CN7.9
N16817854: length 3
  TOP w0.15: 12.1,26 10.11,26
  TOP w0.8: R102.1 12.1,26
  TOP w1: 10.11,26 CN7.8
N16817859: length 3
  TOP w0.15: 12.1,28 10.11,28
  TOP w0.8: R101.1 12.1,28
  TOP w1: 10.11,28 CN7.7
N16817864: length 3
  TOP w0.15: 12.1,30 10.11,30
  TOP w0.8: R100.1 12.1,30
  TOP w1: 10.11,30 CN7.6
N16817869: length 3
  TOP w0.15: 12.1,32 10.11,32
  TOP w0.8: R97.1 12.1,32
  TOP w1: 10.11,32 CN7.5
N16817874: length 3
  TOP w0.15: 12.1,34 10.11,34
  TOP w0.8: R99.1 12.1,34
  TOP w1: 10.11,34 CN7.4
N16817879: length 3
  TOP w0.15: 12.1,36 10.11,36
  TOP w0.8: R98.1 12.1,36
  TOP w1: 10.11,36 CN7.3
N16817884: length 3
  TOP w0.15: 12.1,38 10.11,38
  TOP w0.8: R96.1 12.1,38
  TOP w1: 10.11,38 CN7.2

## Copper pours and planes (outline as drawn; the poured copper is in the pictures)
1.2V on TOP: 79,54 78.75,54.07 78.57,54.25 78.5,54.5 78.5,56.29 78.54,56.48 78.65,56.65 80.85,58.85 81.02,58.96 81.21,59 91.71,59 91.75,58.99 91.78,58.97 92.22,58.53 92.24,58.5 92.25,58.46 92.25,57.33 92.24,57.3 92.23,57.27 92.16,57.16 92.12,57.04 92.1,57 92.06,56.98 91.78,56.75 91.67,56.4 91.67,56.26 91.66,56.2 91.61,56.17 91.49,56.11 91.38,56.03 91.35,56.01 91.31,56 90.5,56 90.43,56.03 90.4,56.1 90.4,56.4 90.17,56.97 89.6,57.2 87.9,57.2 87.33,56.97 87.1,56.4 87.1,56.1 87.07,56.03 87,56 83.21,56 82.96,55.93 82.85,55.85 81.15,54.15 81.04,54.07 80.79,54
1.2V on BOTTOM: 79,54 78.75,54.07 78.57,54.25 78.5,54.5 78.5,56 78.57,56.25 78.75,56.43 79,56.5 80.5,56.5 80.75,56.43 80.93,56.25 81,56 81,54.5 80.93,54.25 80.75,54.07 80.5,54
1.2V on CONDUCTIVE3: 54.71,29 54.58,29.02 54.35,29.15 54.15,29.35 54.07,29.46 54,29.71 54,52.29 54.02,52.42 54.15,52.65 54.6,53.1 54.71,53.18 54.96,53.25 74.04,53.25 74.29,53.32 74.4,53.4 77.93,56.93 78.01,56.98 78.1,57 80.4,57 80.49,56.98 80.57,56.93 81.43,56.07 81.48,55.99 81.5,55.9 81.5,53.6 81.48,53.51 81.43,53.43 79.15,51.15 79.02,50.92 79,50.79 79,37.96 78.98,37.83 78.85,37.6 78.65,37.4 78.54,37.32 78.29,37.25 69.75,37.25 69.28,37.16 68.87,36.88 68.6,36.49 68.5,36 68.5,31.1 68.48,31.01 68.43,30.93 68.06,30.56 68,30.52 67.93,30.49 67.62,30.33 67.5,30 67.5,29.6 67.48,29.51 67.43,29.43 67.07,29.07 66.99,29.02 66.9,29
3.3V on TOP: 18.2,40.7 18.1,40.73 18.03,40.8 18,40.9 18,43.1 18.03,43.2 18.1,43.27 18.2,43.3 19.5,43.3 19.6,43.27 19.67,43.2 19.7,43.1 19.7,40.9 19.67,40.8 19.6,40.73 19.5,40.7
3.3V on TOP: 90.5,45.5 90.43,45.53 90.4,45.6 90.4,45.9 90.17,46.47 89.6,46.7 84.84,46.7 84.8,46.71 84.77,46.73 84.53,46.97 84.51,47 84.5,47.04 84.5,47.96 84.51,48 84.53,48.03 84.97,48.47 85,48.49 85.04,48.5 91.71,48.5 91.75,48.49 91.78,48.47 92.22,48.03 92.24,48 92.25,47.96 92.25,46.83 92.24,46.8 92.23,46.77 92.16,46.66 92.12,46.54 92.1,46.5 92.06,46.48 91.78,46.25 91.67,45.9 91.67,45.76 91.66,45.7 91.61,45.67 91.49,45.61 91.38,45.53 91.35,45.51 91.31,45.5
3.3V on TOP: 89,37.65 88.88,37.68 88.78,37.77 88.75,37.9 88.75,39.21 88.76,39.25 88.78,39.28 89.22,39.72 89.25,39.74 89.29,39.75 92.21,39.75 92.25,39.74 92.28,39.72 92.72,39.28 92.74,39.25 92.75,39.21 92.75,37.9 92.72,37.77 92.62,37.68 92.5,37.65 92.25,37.65 92.18,37.68 92.15,37.75 92.15,38 91.92,38.57 91.35,38.8 90.65,38.8 90.08,38.57 89.85,38 89.85,37.75 89.82,37.68 89.75,37.65
3.3V on BOTTOM: 85,46.75 84.75,46.82 84.57,47 84.5,47.25 84.57,47.5 84.75,47.68 85,47.75 89.5,47.75 89.75,47.68 89.93,47.5 90,47.25 89.93,47 89.75,46.82 89.5,46.75
3.3V on BOTTOM: 89.25,37.75 89,37.82 88.82,38 88.75,38.25 88.75,39.25 88.82,39.5 89,39.68 89.25,39.75 91,39.75 91.25,39.68 91.43,39.5 91.5,39.25 91.5,38.25 91.43,38 91.25,37.82 91,37.75
3.3V on CONDUCTIVE3: outline of 188 points within 1.5,7 98.5,73.5
3.3VA on TOP: 89.29,30.25 89.25,30.26 89.22,30.28 88.78,30.72 88.76,30.75 88.75,30.79 88.75,35.81 88.76,35.85 88.78,35.88 89.22,36.32 89.25,36.34 89.29,36.35 89.75,36.35 89.82,36.32 89.85,36.24 89.85,36.2 89.85,36 90.08,35.43 90.65,35.2 91.35,35.2 91.92,35.43 92.15,36 92.15,36.2 92.15,36.24 92.18,36.32 92.25,36.35 92.65,36.35 92.72,36.32 92.75,36.25 92.75,35.29 92.74,35.25 92.72,35.22 92.03,34.53 92,34.51 91.95,34.5 91.49,34.31 91.3,33.85 91.3,33.16 91.28,33.1 90.92,32.77 90.8,32.35 90.8,30.5 90.77,30.38 90.67,30.28 90.55,30.25
3.3VA on BOTTOM: 90.25,30.25 90,30.32 89.82,30.5 89.75,30.75 89.75,33.75 89.82,34 90,34.18 90.25,34.25 90.75,34.25 91,34.18 91.18,34 91.25,33.75 91.25,30.75 91.18,30.5 91,30.32 90.75,30.25
3.3VA on CONDUCTIVE3: 70.21,23 70.08,23.02 69.85,23.15 69.65,23.35 69.54,23.52 69.5,23.71 69.5,26.29 69.52,26.42 69.65,26.65 69.85,26.85 70.01,26.96 70.2,27 70.2,27 78.29,27 78.85,27.11 79.35,27.44 79.56,27.65 79.88,28.12 80,28.71 80,35.54 80.02,35.67 80.15,35.9 80.35,36.1 80.46,36.18 80.71,36.25 90.79,36.25 90.92,36.23 91.15,36.1 91.85,35.4 91.93,35.29 92,35.04 92,24.21 91.98,24.08 91.85,23.85 91.15,23.15 91.04,23.07 90.79,23
3V_REF on BOTTOM: 74.2,36.5 74.35,36.85 74.7,37 79.5,37 79.85,36.85 80,36.5 80,30.71 80.04,30.52 80.15,30.35 80.35,30.15 80.52,30.04 80.71,30 86.79,30 86.98,29.96 87.15,29.85 88.35,28.65 88.52,28.54 88.71,28.5 90,28.5 90.35,28.35 90.5,28 90.5,26 90.43,25.75 90.25,25.57 90,25.5 88.21,25.5 88.08,25.52 87.85,25.65 85.65,27.85 85.42,27.98 85.29,28 73.7,28 73.45,28.07 73.27,28.25 73.2,28.5 73.2,29.12 73.24,29.2 73.32,29.22 74.13,29.51 74.21,30.37 74.2,30.39 74.2,30.41 ; 1 cut-out
3V_REF on CONDUCTIVE3: 70.21,28 70.08,28.02 69.85,28.15 69.65,28.35 69.57,28.46 69.5,28.71 69.5,35.54 69.52,35.67 69.65,35.9 69.85,36.1 69.96,36.18 70.21,36.25 78.29,36.25 78.42,36.23 78.65,36.1 78.85,35.9 78.93,35.79 79,35.54 79,28.71 78.98,28.58 78.85,28.35 78.65,28.15 78.54,28.07 78.29,28
5V on TOP: 93.42,55.5 93.35,55.53 93.33,55.6 93.33,56.4 93.22,56.75 92.94,56.98 92.9,57 92.88,57.04 92.84,57.16 92.77,57.27 92.76,57.3 92.75,57.33 92.75,58.46 92.76,58.5 92.78,58.53 93.22,58.97 93.25,58.99 93.29,59 97.01,59 97.05,58.99 97.08,58.97 97.52,58.53 97.54,58.5 97.55,58.46 97.55,56.49 97.54,56.45 97.52,56.42 97.13,56.03 97.1,56.01 97.06,56 96.5,56 96.43,56.03 96.4,56.1 96.4,56.4 96.17,56.97 95.6,57.2 95.4,57.2 94.83,56.97 94.6,56.4 94.6,55.6 94.57,55.53 94.5,55.5
5V on TOP: 48.56,4.9 48.48,4.92 48.42,4.96 48.18,5.19 48.14,5.26 48.12,5.33 48.12,5.85 47.96,6.24 47.58,6.4 46.93,6.4 46.87,6.42 46.84,6.47 46.81,6.54 46.77,6.6 46.75,6.63 46.75,6.66 46.75,6.77 46.77,6.84 46.81,6.91 47.04,7.14 47.11,7.18 47.18,7.2 49.22,7.2 49.27,7.19 49.36,7.14 49.64,6.86 49.67,6.82 49.7,6.72 49.7,5.28 49.69,5.23 49.64,5.14 49.46,4.96 49.42,4.93 49.32,4.9
5V on TOP: 86,10.5 85.75,10.57 85.57,10.75 85.5,11 85.5,14 85.57,14.25 85.75,14.43 86,14.5 86.5,14.5 86.57,14.47 86.6,14.4 86.6,14.1 86.83,13.53 87.4,13.3 87.6,13.3 88.17,13.53 88.4,14.1 88.4,14.4 88.43,14.47 88.5,14.5 88.9,14.5 88.97,14.47 89,14.4 89,13.6 89.18,13.18 89.6,13 90.5,13 90.5,14.15 90.53,14.22 90.6,14.25 91.4,14.25 91.47,14.22 91.5,14.15 91.5,11 91.43,10.75 91.25,10.57 91,10.5
5V on TOP: 18.2,56.7 18.1,56.73 18.03,56.8 18,56.9 18,59.1 18.03,59.2 18.1,59.27 18.2,59.3 19.45,59.3 19.55,59.27 19.62,59.2 19.65,59.1 19.65,56.9 19.62,56.8 19.55,56.73 19.45,56.7
5V on BOTTOM: 19.05,59 19.35,59.3 19.65,59 19.65,57 19.35,56.7 19.05,57
5V on BOTTOM: 86,10.5 85.75,10.57 85.57,10.75 85.5,11 85.5,14 85.57,14.25 85.75,14.43 86,14.5 86.25,14.43 86.43,14.25 86.5,14 86.5,11 86.43,10.75 86.25,10.57
5V on BOTTOM: 95.5,46.75 95.25,46.82 95.07,47 95,47.25 95.07,47.5 95.25,47.68 95.5,47.75 97,47.75 97.25,47.68 97.43,47.5 97.5,47.25 97.43,47 97.25,46.82 97,46.75
5V on BOTTOM: 95.5,57.25 95.25,57.32 95.07,57.5 95,57.75 95.07,58 95.25,58.18 95.5,58.25 97,58.25 97.25,58.18 97.43,58 97.5,57.75 97.43,57.5 97.25,57.32 97,57.25
5V on CONDUCTIVE3: outline of 138 points within 1.5,1.2 98.5,61.5
GND on TOP: 76.05,11.65 75.94,11.69 75.9,11.8 75.9,12.26 75.85,12.49 75.72,12.69 75.46,12.95 75.38,12.99 75.32,13.05 75.3,13.13 75.3,15.88 75.32,15.96 75.38,16.01 75.45,16.06 75.51,16.11 75.72,16.33 75.76,16.38 75.81,16.43 75.88,16.45 76.34,16.45 77.15,17.25 76.34,18.05 76,18.05 75.89,18.09 75.85,18.2 75.85,19.19 75.86,19.25 75.89,19.3 77,20.41 77.05,20.44 77.11,20.45 78,20.45 78.11,20.41 78.15,20.3 78.15,16.69 78.2,16.46 78.33,16.26 78.55,16.05 78.62,16.01 78.68,15.94 78.7,15.86 78.7,15.8 78.7,15.45 78.66,15.34 78.55,15.3 77.81,15.3 77,14.5 77.81,13.7 78.55,13.7 78.66,13.66 78.7,13.55 78.7,13.2 78.7,13.14 78.69,13.05 78.62,12.99 78.55,12.94 78.49,12.89 78.25,12.64 78.22,12.61 78.17,12.57 78.1,12.55 77.66,12.55 77.1,12.33 76.85,11.79 76.8,11.69 76.7,11.65
GND on TOP: 27.82,36.58 27.72,36.62 27.68,36.73 27.68,38 27.72,38.11 27.82,38.15 33.1,38.15 33.21,38.11 33.25,38 33.25,36.73 33.21,36.62 33.1,36.58
GND on TOP: 67.15,10.85 67.04,10.89 67,11 67,12.09 67.01,12.14 67.16,12.38 67.2,12.6 67.2,12.98 67.22,13.04 67.51,13.38 67.6,13.74 67.6,15.26 67.51,15.62 67.22,15.96 67.2,16.02 67.2,16.4 67.15,16.63 67.02,16.82 66.89,16.96 66.69,17.09 66.46,17.14 66.41,17.14 66.26,17.22 66.04,17.29 65.92,17.3 65,17.3 64.89,17.34 64.85,17.45 64.85,21.39 64.86,21.45 64.89,21.5 65.4,22.01 65.45,22.04 65.52,22.05 67.75,22.05 67.86,22.01 67.9,21.9 67.9,11.06 67.89,11 67.86,10.95 67.8,10.89 67.75,10.86 67.69,10.85
GND on TOP: outline of 202 points within 49.2,25.57 77.5,52.5
GND on TOP: 48.33,43.05 48.27,43.06 48.22,43.09 44.44,46.87 44.41,46.92 44.4,46.98 44.4,47.25 44.44,47.36 44.55,47.4 44.72,47.4 44.78,47.39 44.83,47.36 46.24,45.94 46.43,45.82 46.65,45.77 48.15,45.77 48.26,45.73 48.3,45.62 48.3,44.65 48.53,44.08 49.1,43.85 52.05,43.85 52.16,43.81 52.2,43.7 52.2,43.2 52.16,43.09 52.05,43.05
GND on TOP: 45.6,39.17 45.52,39.2 45.45,39.27 45.52,39.35 45.6,39.38 45.62,39.45 45.7,39.52 45.77,39.45 45.77,39.1 45.7,39.02 45.62,39.1
GND on TOP: outline of 1487 points within 0.5,0.5 99.5,74.5 ; 26 cut-outs
GND on TOP: 72.6,54.8 72.49,54.84 72.45,54.95 72.45,55.25 72.48,55.34 72.57,55.39 72.61,55.4 72.75,55.4 73.53,56.01 73.11,56.92 72.95,56.97 72.79,57 72.69,57.05 72.65,57.15 72.65,58.48 72.69,58.58 72.8,58.62 74.7,58.62 74.81,58.58 74.85,58.48 74.85,57.15 74.81,57.05 74.71,57 74.6,56.99 74.5,56.96 74.29,56.85 74.12,56.69 73.95,56.2 74.12,55.71 74.4,55.48 74.75,55.4 74.89,55.4 74.93,55.39 75.02,55.34 75.05,55.25 75.05,54.95 75.01,54.84 74.9,54.8
GND on TOP: 61.55,11.65 61.44,11.69 61.4,11.8 61.4,12.26 61.35,12.49 61.22,12.69 60.96,12.95 60.88,12.99 60.82,13.05 60.8,13.13 60.8,15.88 60.82,15.96 60.88,16.01 60.95,16.06 61.01,16.11 61.17,16.28 61.22,16.33 61.26,16.38 61.31,16.43 61.38,16.45 61.84,16.45 62.65,17.25 61.84,18.05 61.5,18.05 61.39,18.09 61.35,18.2 61.35,19.19 61.36,19.25 61.39,19.3 62.5,20.41 62.55,20.44 62.61,20.45 63.5,20.45 63.61,20.41 63.65,20.3 63.65,16.69 63.7,16.46 63.83,16.26 64.05,16.05 64.12,16.01 64.18,15.94 64.2,15.86 64.2,15.8 64.2,15.45 64.16,15.34 64.05,15.3 63.31,15.3 62.5,14.5 63.31,13.7 64.05,13.7 64.16,13.66 64.2,13.55 64.2,13.2 64.2,13.14 64.19,13.05 64.13,12.99 64.05,12.94 63.99,12.89 63.75,12.64 63.72,12.61 63.67,12.57 63.6,12.55 63.16,12.55 62.6,12.33 62.35,11.79 62.3,11.69 62.2,11.65
GND on TOP: 81.65,10.85 81.54,10.89 81.5,11 81.5,12.09 81.51,12.14 81.66,12.38 81.7,12.6 81.7,12.98 81.72,13.04 82.01,13.38 82.1,13.74 82.1,15.26 82.01,15.62 81.72,15.96 81.7,16.02 81.7,16.4 81.65,16.63 81.52,16.82 81.39,16.96 81.19,17.09 80.96,17.14 80.91,17.14 80.76,17.22 80.54,17.29 80.42,17.3 79.5,17.3 79.39,17.34 79.35,17.45 79.35,21.44 79.44,21.58 79.61,21.55 82.36,18.8 82.39,18.75 82.4,18.69 82.4,11.06 82.39,11 82.36,10.95 82.3,10.89 82.25,10.86 82.19,10.85
GND on TOP: 69.1,54.8 68.99,54.84 68.95,54.95 68.95,55.25 68.98,55.34 69.07,55.39 69.11,55.4 69.25,55.4 70.05,56.18 69.29,57 69.19,57.05 69.15,57.15 69.15,58.48 69.19,58.58 69.3,58.62 70.7,58.62 70.81,58.58 70.85,58.48 70.85,54.95 70.81,54.84 70.7,54.8
GND on TOP: 45.6,29.17 45.52,29.2 45.45,29.27 45.52,29.35 45.6,29.38 45.62,29.45 45.7,29.52 45.77,29.45 45.77,29.1 45.7,29.02 45.62,29.1
